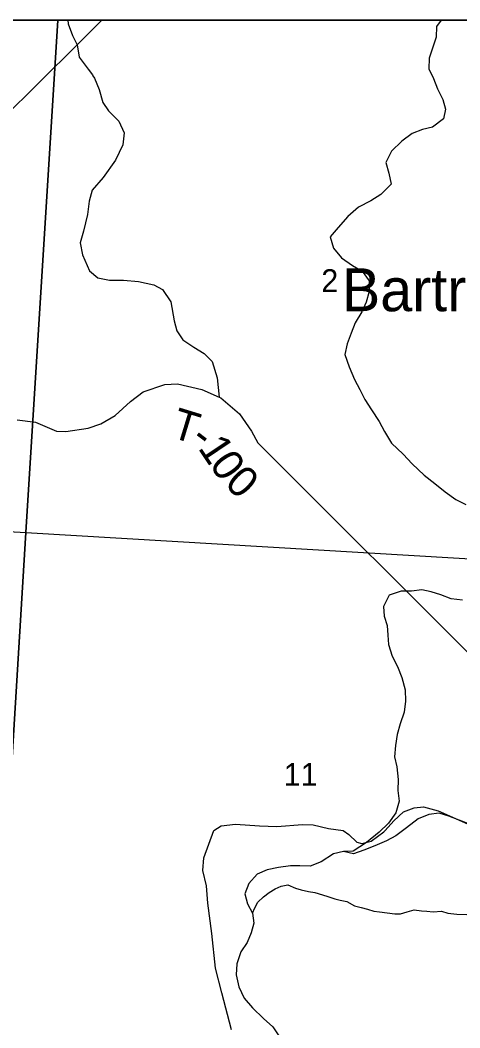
# Model space of a CAD drawing. Extents: x 0 to 34, y 0 to 22.
# Drawn here: x 6.969 to 7.778, y 19.045 to 20.9 of the extents above; entities that cross this region are included whole.
import ezdxf

# ---------------------------------------------------------------- set-up
doc = ezdxf.new("R2010")
doc.units = 0
for name, color, linetype in [('GM_X_County', 7, 'Continuous'), ('GM_X_County_Road', 7, 'Continuous'), ('GM_X_Minor_River', 7, 'Continuous'), ('GM_X_Section', 7, 'Continuous'), ('GM_X_Section_Text', 7, 'Continuous'), ('GM_X_Township', 7, 'Continuous'), ('GM_X_Township_Road', 7, 'Continuous'), ('GM_X_Township_Road_Text', 7, 'Continuous'), ('GM_X_Township_ROW', 7, 'Continuous'), ('GM_X_Unincorporated_Text', 7, 'Continuous'), ('SH_Data', 7, 'Continuous')]:
    doc.layers.add(name, color=color, linetype=linetype)

msp = doc.modelspace()

# ---------------------------------------------------------------- linework, layer by layer
at = {"layer": 'GM_X_County'}
msp.add_lwpolyline([(9.4175, 16.6203), (9.4175, 20.9), (2.6175, 20.9), (2.6175, 15.1694)], dxfattribs=at)
at = {"layer": 'GM_X_County_Road'}
for points in [[(7.6403, 19.4086), (7.6564, 19.4261), (7.6738, 19.4429), (7.6937, 19.4503), (7.7109, 19.4522), (7.738, 19.4446), (7.8456, 19.397), (7.8695, 19.3955), (7.885, 19.4016), (7.9051, 19.4157), (7.918, 19.4176), (7.9357, 19.4163)], [(7.3579, 19.0412), (7.3399, 19.1094), (7.3284, 19.1549), (7.3214, 19.2186), (7.3141, 19.2748), (7.3118, 19.3062), (7.3049, 19.3347), (7.3067, 19.3578), (7.3255, 19.4083), (7.3388, 19.4171), (7.3653, 19.4202), (7.4093, 19.4169), (7.4411, 19.4158), (7.4881, 19.4193), (7.5082, 19.4186), (7.5359, 19.4118), (7.5632, 19.4081), (7.5738, 19.4009), (7.5883, 19.3869), (7.5974, 19.3843), (7.6148, 19.3889), (7.6379, 19.406), (7.6385, 19.4067), (7.6403, 19.4086)]]:
    msp.add_lwpolyline(points, dxfattribs=at)
at = {"layer": 'GM_X_Minor_River'}
for points in [[(7.7345, 20.8884), (7.7343, 20.8687), (7.7214, 20.83), (7.7206, 20.8103), (7.7289, 20.7928), (7.7364, 20.7738), (7.7462, 20.7541), (7.7515, 20.7359), (7.7477, 20.7185), (7.7272, 20.7033), (7.7091, 20.6988), (7.6901, 20.6912), (7.6712, 20.6775), (7.6522, 20.6586), (7.6416, 20.6381), (7.6469, 20.6184), (7.6514, 20.5979), (7.6324, 20.579), (7.6142, 20.5676), (7.5915, 20.5555), (7.5718, 20.5388), (7.5536, 20.5183), (7.5392, 20.5009), (7.5452, 20.4804), (7.5603, 20.4622), (7.58, 20.4485), (7.5981, 20.4379), (7.611, 20.4204), (7.6109, 20.4007), (7.6056, 20.381), (7.5972, 20.3628), (7.5851, 20.3431), (7.5775, 20.3241), (7.5706, 20.3044), (7.5661, 20.2847), (7.5744, 20.2619), (7.5842, 20.2384), (7.594, 20.2202), (7.603, 20.202), (7.6151, 20.183), (7.6295, 20.161), (7.6393, 20.1428), (7.6521, 20.1215), (7.6733, 20.101), (7.6899, 20.0836), (7.7118, 20.0623), (7.7315, 20.0471), (7.7504, 20.0319), (7.77, 20.0175), (7.7889, 20.0084)], [(7.7432, 20.9), (7.7345, 20.8884)], [(7.7826, 19.8324), (7.7614, 19.8347), (7.7425, 19.8423), (7.7251, 19.8476), (7.7077, 19.8514), (7.6888, 19.8492), (7.6698, 19.8492), (7.6479, 19.8416), (7.6372, 19.8204), (7.6387, 19.8029), (7.644, 19.7855), (7.6455, 19.768), (7.6462, 19.7506), (7.653, 19.7293), (7.6628, 19.7104), (7.6711, 19.6899), (7.6771, 19.6671), (7.6778, 19.6466), (7.6755, 19.6262), (7.6679, 19.6049), (7.6626, 19.5852), (7.6595, 19.5647), (7.6572, 19.5442), (7.6617, 19.5253), (7.664, 19.5025), (7.6639, 19.482), (7.6662, 19.4623), (7.6601, 19.4411), (7.6464, 19.4221), (7.629, 19.4054), (7.6062, 19.3865), (7.5812, 19.3706), (7.5638, 19.3698), (7.5456, 19.3653)], [(7.794, 19.4205), (7.7766, 19.4273), (7.7577, 19.4349), (7.7396, 19.4403), (7.7206, 19.438), (7.7009, 19.4297), (7.6797, 19.413), (7.66, 19.3986), (7.6426, 19.3895), (7.6214, 19.3804), (7.6009, 19.3721), (7.582, 19.3653), (7.5638, 19.3698)], [(7.5456, 19.3653), (7.5229, 19.3509), (7.5025, 19.3426), (7.4835, 19.3433), (7.4661, 19.3434), (7.4442, 19.3403), (7.423, 19.3358), (7.4048, 19.3282), (7.3896, 19.3108), (7.382, 19.2918), (7.3873, 19.2736), (7.3963, 19.2562), (7.3986, 19.238), (7.394, 19.2198), (7.3864, 19.2023), (7.375, 19.1849), (7.3674, 19.1629), (7.3666, 19.1424), (7.3711, 19.1204), (7.3809, 19.0999), (7.3961, 19.0817), (7.4165, 19.062), (7.4339, 19.0468), (7.4474, 19.027)], [(7.3963, 19.2562), (7.4007, 19.2663), (7.406, 19.2762), (7.4166, 19.286), (7.4268, 19.2944), (7.4378, 19.3012), (7.4492, 19.3058), (7.4613, 19.3084), (7.4753, 19.3024), (7.4859, 19.2989), (7.4995, 19.2959), (7.5109, 19.294), (7.5253, 19.2902), (7.5351, 19.2868), (7.5476, 19.2823), (7.5578, 19.2804), (7.5699, 19.2774), (7.5839, 19.2698), (7.5961, 19.2664), (7.6078, 19.2637), (7.6195, 19.26), (7.6298, 19.2585), (7.6582, 19.2547), (7.6688, 19.2551), (7.6809, 19.2589), (7.6934, 19.2623), (7.7074, 19.2604), (7.7172, 19.2596), (7.7286, 19.2585), (7.7437, 19.26), (7.7555, 19.2562), (7.7721, 19.2543), (7.7903, 19.2536)]]:
    msp.add_lwpolyline(points, dxfattribs=at)
at = {"layer": 'GM_X_Section'}
for p, q in [((7.0384, 20.9), (5.9593, 20.9)), ((8.1151, 20.9), (7.0384, 20.9))]:
    msp.add_line(p, q, dxfattribs=at)
for points in [[(5.9593, 20.9), (5.9068, 20.018), (6.9795, 19.9566), (7.0384, 20.9)], [(7.0384, 20.9), (6.9795, 19.9566), (8.0453, 19.8934), (8.1151, 20.9)]]:
    msp.add_lwpolyline(points, dxfattribs=at)
for points in [[(5.9068, 20.018), (6.9795, 19.9566), (6.9173, 18.9472), (5.8458, 19.0101)], [(6.9795, 19.9566), (8.0453, 19.8934), (7.9764, 18.8836), (6.9173, 18.9472)]]:
    msp.add_lwpolyline(points, close=True, dxfattribs=at)
at = {"layer": 'GM_X_Township'}
msp.add_line((8.2133, 20.9), (2.7154, 20.9), dxfattribs=at)
at = {"layer": 'GM_X_Township_Road'}
for points in [[(7.057, 20.9), (7.0576, 20.893), (7.0651, 20.8715), (7.0741, 20.8548), (7.0777, 20.8316), (7.0944, 20.81), (7.1018, 20.7991), (7.1028, 20.7977)], [(7.1028, 20.7977), (7.1058, 20.7933), (7.1142, 20.7721), (7.1211, 20.7486), (7.1317, 20.733), (7.1507, 20.7141), (7.1603, 20.6925), (7.158, 20.6705), (7.1445, 20.6424), (7.1214, 20.6105), (7.1017, 20.5873), (7.0957, 20.5668), (7.0928, 20.5421), (7.0856, 20.5114), (7.0792, 20.4901), (7.0835, 20.4678), (7.0964, 20.4386), (7.112, 20.4257), (7.1332, 20.4212), (7.159, 20.4216), (7.1867, 20.4187), (7.2147, 20.4127), (7.2307, 20.4044), (7.2459, 20.3816), (7.2524, 20.3467), (7.257, 20.3282), (7.2684, 20.3115), (7.2886, 20.2983), (7.3072, 20.2865), (7.322, 20.2718), (7.3315, 20.2414), (7.3353, 20.2059)], [(6.9636, 20.1644), (6.997, 20.1599), (7.019, 20.1508), (7.0361, 20.1433), (7.0528, 20.1426), (7.0941, 20.1491), (7.1176, 20.1567), (7.1437, 20.1724), (7.1717, 20.1978), (7.1955, 20.2157), (7.2353, 20.2295), (7.2584, 20.2307), (7.3031, 20.2201), (7.3353, 20.2059), (7.338, 20.2047), (7.3726, 20.1755), (7.3943, 20.1433), (7.4061, 20.1217), (7.8271, 19.7012)]]:
    msp.add_lwpolyline(points, dxfattribs=at)
at = {"layer": 'GM_X_Township_ROW'}
msp.add_lwpolyline([(6.9068, 20.7107), (6.9354, 20.7171), (7.0741, 20.8548), (7.1195, 20.9)], dxfattribs=at)
at = {"layer": 'SH_Data'}
msp.add_line((2.6, 20.9), (9.4, 20.9), dxfattribs=at)

# ---------------------------------------------------------------- texts
at = {"layer": 'GM_X_Section_Text'}
for s, height, p in [('2', 0.0419, (7.5229, 20.3996)), ('11', 0.04186, (7.4537, 19.4906))]:
    msp.add_text(s, height=height, rotation=0, dxfattribs=at).set_placement(p)
at = {"layer": 'GM_X_Township_Road_Text'}
for s, rotation, p in [('T', 343.0417, (7.2439, 20.133)), ('-', 322.7632, (7.2798, 20.123)), ('1', 303.8265, (7.295, 20.1125)), ('0', 305.5259, (7.3156, 20.0819)), ('0', 315.6768, (7.343, 20.0451))]:
    msp.add_text(s, height=0.0568, rotation=rotation, dxfattribs=at).set_placement(p)
at = {"layer": 'GM_X_Unincorporated_Text'}
msp.add_text('Bartramville', height=0.078977, rotation=0, dxfattribs=at).set_placement((7.5608, 20.3642))

doc.saveas('drawing.dxf')
